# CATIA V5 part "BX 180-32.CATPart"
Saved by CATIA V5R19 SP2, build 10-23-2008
Part number: BX 180-32
Bounding box of the stored display mesh (mm): x -24.865 to 24.865, y -24.997 to 24.997, z 0 to 162
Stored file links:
  C:\Users\Bora\Desktop\3D Katı model\BX serisi\BX 180\BX 180-32.CATPart
  C:\Program Files\Dassault Systemes\B19\intel_a\reffiles\standard\MetricThickPitch.txt
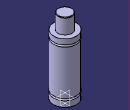
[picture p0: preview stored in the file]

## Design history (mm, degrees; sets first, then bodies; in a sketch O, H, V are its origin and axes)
Body1 (main body)
  Sketch1 on yz-plane, origin (0, 0, 0), H (0, 1, 0), V (0, 0, 1)
    point P2 (25, 12.5)
    line L1 (25, 12.5) -> (25, 0)
    point P3 (25, 16.5)
    point P4 (25, 113.5)
    line L2 (25, 113.5) -> (25, 16.5)
    point P6 (15, 161)
    arc A1 centre (14, 161) radius 1 from (15, 161) to (14, 162) ccw
    point P8 (15, 161)
    line L3 (15, 161) -> (15, 129)
    point P9 (25, 117.5)
    line L4 (25, 129) -> (25, 117.5)
    point P11 (25, 113.5)
    point P12 (25, 117.5)
    arc A2 centre (25, 115.5) radius 2 from (25, 117.5) to (25, 113.5) ccw
    point P13 (25, 12.5)
    point P14 (25, 16.5)
    arc A3 centre (25, 14.5) radius 2 from (25, 16.5) to (25, 12.5) ccw
    line L5 (14, 162) -> (0, 162)
    line L6 (15, 129) -> (25, 129)
    line L7 (25, 0) -> (0, 0)
    tangency: L5 A1
    horizontal: L6 H, L7 H
    coincidence: P2 P13, P3 P14, P4 P11, P6 P8, P9 P12
  Shaft1: profile Sketch1, axis Sketch1.V, angle 360
  Sketch2 on face of Shaft1 from Sketch1.L7, origin (0, 0, 0), H (1, 0, 0), V (0, -1, 0)
    point P1 (12.5, 0)
    distance P1 V = 12.5
  Hole1: placed by Sketch2, at (12.5, 0, 0) direction (0, 0, 1), diameter 4.917, depth 6, threaded "M6", thread diameter 6, thread depth 6, pitch 1
  Sketch3 on face of Shaft1 from Sketch1.L7, origin (0, 0, 0), H (1, 0, 0), V (0, -1, 0)
    point P1 (-12.5, 0)
    distance P1 V = 12.5
  Hole2: placed by Sketch3, at (-12.5, 0, 0) direction (0, 0, 1), diameter 4.917, depth 6, threaded "M6", thread diameter 6, thread depth 6, pitch 1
